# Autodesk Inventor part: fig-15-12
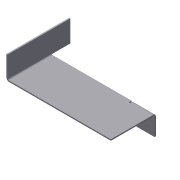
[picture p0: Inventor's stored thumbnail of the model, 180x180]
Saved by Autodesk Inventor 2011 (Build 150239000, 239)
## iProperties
Shininess: 77.0
Angle Display Precision: 2
Document Length Units: 11269
Document Angle Units: 11279
Document Time Units: 11290
Document Mass Units: 11283
Document Length Units Precision: 3
Document Angle Units Precision: 2
Created: 2002-04
Part Number: fig-15-12
Material: Aluminum-6061
Document SubType Name: Sheet Metal
Density: 1 g/cm^3
Sheet Metal Rule: Default
Density: 0.0
Volumn: 0.0
Area: 0.0
PropertySet Name: Model Information
Control State: 0
Master: False
Checked Out: False
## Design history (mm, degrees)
node "Face1"
  sketch "Sketch1"
    geometry: L1 (-49.559, 19.574)-(-49.559, -30.426); L2 (-49.559, -30.426)-(50.441, -30.426); L3 (50.441, -30.426)-(50.441, 19.574); L4 (50.441, 19.574)-(32.941, 19.574); L5 (32.941, 19.574)-(32.941, 4.574); L6 (32.941, 4.574)-(-32.059, 4.574); L7 (-32.059, 4.574)-(-32.059, 19.574); L8 (-32.059, 19.574)-(-49.559, 19.574)
    constraints: 16 end point, 6 parallel, 2 equal length, 1 perpendicular, 1 vertical
    dimensions: "d0" = 100 distance of L1.end L2.end; "d1" = 65 distance of L5.end L6.end; "d2" = 15 distance of L6.end L7.end; "d3" = 50 distance of L1.start L1.end
sketch "Sketch2"
  geometry: L1 (100, 0)-(0, 0) reference; L2 (17.5, 50)-(17.5, 35) reference; L3 (82.5, 50)-(82.5, 0)
  constraints: 2 end point, 1 parallel, 1 point on line
sketch "Sketch3"
  geometry: L1 (81.369, -50)-(0, -50) reference; L2 (17.5, 0)-(17.5, -50)
  constraints: 2 end point, 1 perpendicular, 1 point on line
feature "Fold2" sketch "Sketch3" dims "d8" = 1 (= BendRadius), "d9" = 90 deg, "d10" = 1 (= BendRadius), "d14" = 1 (= BendReliefWidth), "d15" = 0.5 (= BendReliefDepth), "d16" = 2 (= MinimumRemnant), "SeamGap" = 0.01, "Thickness" = 1
sketch "Sketch4"
  geometry: L1 (17.5, 0)-(17.5, -50) reference; L2 (-63.869, -15)-(0, -15) reference; L3 (0, -15)-(17.5, -15)
  constraints: 2 end point, 1 collinear, 1 point on line
feature "Fold3" sketch "Sketch4" dims "d11" = 1 (= BendRadius), "d12" = 90 deg, "d13" = 1, "d17" = 1 (= BendReliefWidth), "d18" = 1, "d19" = 2 (= MinimumRemnant), "SeamGap" = 0.01, "Thickness" = 1
body "Solid1"
face "Plate1" dims "Thickness" = 1
other parameters: "BendRadius" = 1 (= Thickness), "BendReliefWidth" = 1 (= Thickness), "BendReliefDepth" = 0.5 (= 0.5 x Thickness), "CornerReliefSize" = 4 (= 4 x Thickness), "MinimumRemnant" = 2 (= 2 x Thickness), "TransitionRadius" = 1 (= BendRadius), "d4" = 1 (= BendRadius), "JacobiRadiusSize" = 1 (= Thickness), "GapSize" = 1 (= Thickness)
